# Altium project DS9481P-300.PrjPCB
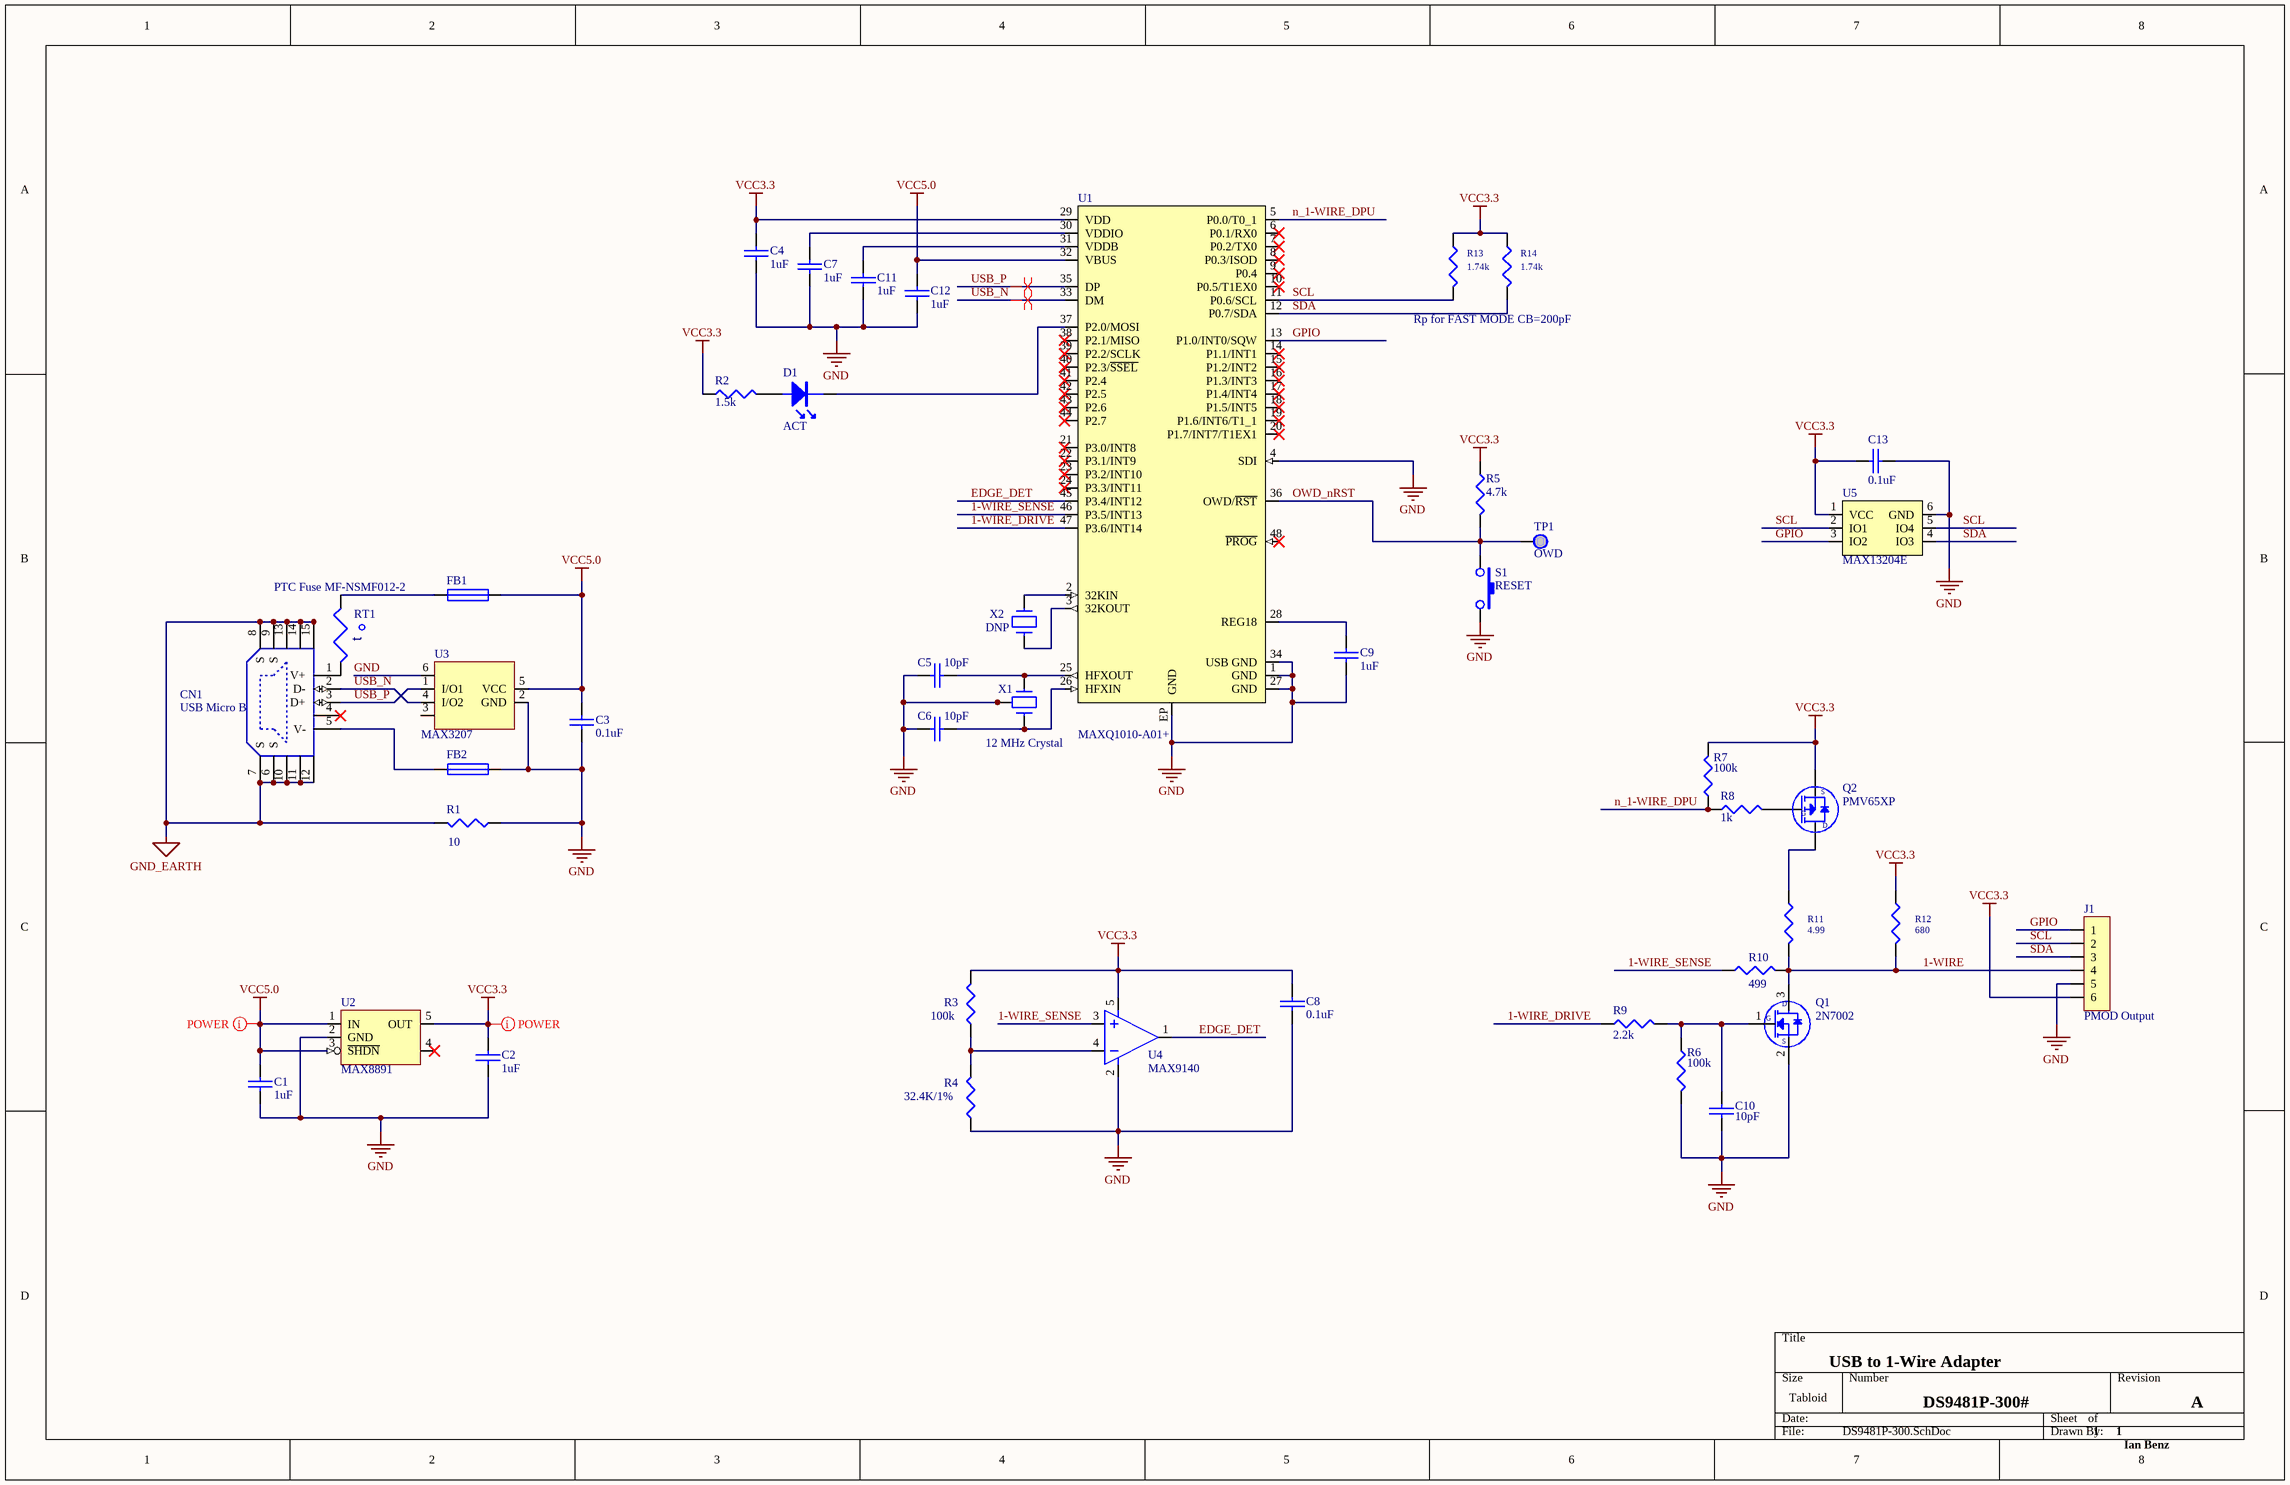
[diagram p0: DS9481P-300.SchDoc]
1 sheet, 44 parts. Net scope: global (net labels, ports and power ports of the same name join across sheets).
Board file: DS9481P-300.PcbDoc

## Sheet DS9481P-300.SchDoc
size Tabloid

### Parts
C1  1uF  [CAP0402-3D]
C2  1uF  [CAP0402-3D]
C3  0.1uF  [CAP0402-3D]
C4  1uF  [CAP0402-3D]
C5  10pF  [CAP0603-3D]
C6  10pF  [CAP0603-3D]
C7  1uF  [CAP0402-3D]
C8  0.1uF  [CAP0402-3D]
C9  1uF  [CAP0402-3D]
C10  10pF  [CAP0402-3D]
C11  1uF  [CAP0402-3D]
C12  1uF  [CAP0402-3D]
C13  0.1uF  [CAP0402-3D]
CN1  USB Micro B  [USBMICROB-3D]
D1  ACT  [0603LED-3DORANGE]
FB1  (no value)  [0603-3D]
FB2  (no value)  [0603-3D]
J1  PMOD Output  [SIP6-SOCKET2-RA-3D]
Q1  2N7002  [16001-3D]
Q2  PMV65XP  [16001-3D]
R1  10  [0603-3D]
R2  1.5k  [0402-3D]
R3  100k  [0402-3D]
R4  32.4K/1%  [0402-3D]
R5  4.7k  [0402-3D]
R6  100k  [0402-3D]
R7  100k  [0402-3D]
R8  1k  [0402-3D]
R9  2.2k  [0402-3D]
R10  499  [0402-3D]
R11  4.99  [0805-3D]
R12  680  [0402-3D]
R13  1.74k  [0402-3D]
R14  1.74k  [0402-3D]
RT1  PTC Fuse MF-NSMF012-2  [1206POLYFUSE-3D]
S1  RESET  [RESET9-3d]
TP1  OWD  [SIP1]  (no BOM)
U1  MAXQ1010-A01+  [TQFN48 6MM]
U2  MAX8891  [SC70-5-3D]
U3  MAX3207  [sot23-6-3D]
U4  MAX9140  [SC70-5-3D]
U5  MAX13204E  [TDFN6 2MM .65]
X1  12 MHz Crystal  [FA-238V]
X2  DNP  [M8]

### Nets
GND: C1.2 C2.2 C3.2 C4.2 C5.2 C6.2 C7.2 C8.2 C9.2 C10.1 C11.2 C12.2 C13.2 FB2.2 J1.5 Q1.2 R1.1 R4.1 R6.1 S1.1 U1.1(GND) U1.4(SDI) U1.27(GND) U1.34(USB_GND) U1.EP(GND) U2.2(GND) U3.2(GND) U3.6 U4.2 U5.6(GND) X1.2(G) X1.4(G)
GND_EARTH: CN1.6(S) CN1.7(S) CN1.8(S) CN1.9(S) CN1.10 CN1.11 CN1.12 CN1.13 CN1.14 CN1.15 CN1.16 R1.2
VCC3.3: C2.1 C4.1 C8.1 C13.1 J1.6 Q2.2 R2.1 R3.2 R5.2 R7.2 R12.2 R13.2 R14.2 U1.29(VDD) U2.5(OUT) U4.5 U5.1(VCC)
VCC5.0: C1.1 C3.1 C12.1 FB1.2 U1.32(VBUS) U2.1(IN) U2.3(~{SHDN}) U3.5(VCC)
1-WIRE: J1.4 Q1.3 R10.2 R11.2 R12.1
1-WIRE_DRIVE: R9.2 U1.47(P3.6/INT14)
1-WIRE_SENSE: R10.1 U1.46(P3.5/INT13) U4.3
EDGE_DET: U1.45(P3.4/INT12) U4.1
GPIO: J1.1 U1.13(P1.0/INT0/SQW) U5.3(IO2)
n_1-WIRE_DPU: R7.1 R8.1 U1.5(P0.0/T0_1)
OWD_nRST: R5.1 S1.2 TP1.1 U1.36(OWD/~{RST})
SCL: J1.2 R13.1 U1.11(P0.6/SCL) U5.2(IO1) U5.5(IO4)
SDA: J1.3 R14.1 U1.12(P0.7/SDA) U5.4(IO3)
USB_N: CN1.2(D-) U1.33(DM) U3.4(I/O2)
USB_P: CN1.3(D+) U1.35(DP) U3.1(I/O1)
NetC5_1: C5.1 U1.25(HFXOUT) X1.1(X1)
NetC6_1: C6.1 U1.26(HFXIN) X1.3(X2)
NetC7_1: C7.1 U1.30(VDDIO)
NetC9_1: C9.1 U1.28(REG18)
NetC10_2: C10.2 Q1.1 R6.2 R9.1
NetC11_1: C11.1 U1.31(VDDB)
NetCN1_1: CN1.1(V+) RT1.1
NetCN1_5: CN1.5(V-) FB2.1
NetD1_1: D1.1 U1.37(P2.0/MOSI)
NetD1_2: D1.2 R2.2
NetFB1_1: FB1.1 RT1.2
NetQ2_1: Q2.1 R8.2
NetQ2_3: Q2.3 R11.1
NetR3_1: R3.1 R4.2 U4.4
NetU1_2: U1.2(32KIN) X2.2
NetU1_3: U1.3(32KOUT) X2.1

Not connected (* = marked no-connect by the designer): CN1 4*; U1 6(P0.1/RX0)* 7(P0.2/TX0)* 8(P0.3/ISOD)* 9(P0.4)* 10(P0.5/T1EX0)* 14(P1.1/INT1)* 15(P1.2/INT2)* 16(P1.3/INT3)* 17(P1.4/INT4)* 18(P1.5/INT5)* 19(P1.6/INT6/T1_1)* 20(P1.7/INT7/T1EX1)* 21(P3.0/INT8)* 22(P3.1/INT9)* 23(P3.2/INT10)* 24(P3.3/INT11)* 38(P2.1/MISO)* 39(P2.2/SCLK)* 40(P2.3/~{SSEL})* 41(P2.4)* 42(P2.5)* 43(P2.6)* 44(P2.7)* 48(~{PROG})*; U2 4*; U3 3

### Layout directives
differential pair: USB_N, USB_P
net class POWER_NETS: VCC3.3, VCC5.0

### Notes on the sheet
- Rp for FAST MODE CB=200pF
- USB to 1-Wire Adapter
- DS9481P-300#
- 1
- A
- Ian Benz

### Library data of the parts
C1 C2 C4 C7 C9 C11 C12 = CAP: CAP CER 1UF 6.3V 20% X5R 0402; Manufacture Name: TDK Corporation; Part Number: C1005X5R0J105M050BB; Internal Part Number: EC1065; Vendor Part Number: 445-1415-1-ND; Vendor: Digi-Key
C3 C8 C13 = CAP: CAP CER 0.1UF 6.3V 10% X5R 0402; Manufacture Name: TDK Corporation; Part Number: C1005X5R0J104K050BA; Internal Part Number: EC1458B; Vendor Part Number: 445-1266-2-ND; Vendor: Digi-Key
C5 C6 = CAP: CAP CER 10PF 50V C0G 0603; Manufacture Name: TDK Corporation; Part Number: C1608C0G1H100D080AA; Internal Part Number: EC0976; Vendor Part Number: 445-1269-1-ND; Vendor: Digi-Key
C10 = CAP: CAP CER 10PF 50V 5% NP0 0402; Manufacture Name: MURATA; Part Number: GRM1555C1H100J; Internal Part Number: ECM0081; Vendor Part Number: 490-5921-1-ND; Vendor: Digi-Key
CN1 = USB-MICRO-B: CONN RCPT STD MICRO USB TYPE B; Internal Part Number: EH1498; Manufacture Name: FCI; Part Number: 10103594-0001LF; Vendor Part Number: 609-4050-1-ND; Vendor: Digi-Key
D1 = LED: LED ORANGE HIGH BRIGHT USS 0603; Manufacture Name: Panasonic; Part Number: LNJ826W83RA; Internal Part Number: ED1021; Vendor Part Number: P13487CT-ND; Vendor: Digi-Key
FB1 FB2 = FUSE1: FERRITE CHIP 220 OHM 2200MA 0603; Part Number: BLM18KG221SN1D; Manufacture Name: Murata Electronics North America; Vendor Part Number: 490-5255-1-ND; Vendor: Digi-Key
J1 = CON6: CONN RCPT .100" 6POS R/A SGL TIN; Manufacture Name: Samtec; Part Number: SSW-106-02-T-S-RA; Vendor Part Number: 82P3428; Vendor: Newark
Q1 = NCHAN FET: MOSFET N-CH 60V 115MA SOT23-3; Manufacture Name: Diodes Inc.; Part Number: 2N7002-7; Internal Part Number: EQ0219
Q2 = PCHAN FET: MOSFET P-CH 20V 2.8A SOT-23; Part Number: PMV65XP,215; Manufacture Name: International Rectifier; Internal Part Number: EQ1054
R1 = RESISTOR: RES SMD 10 OHM 5% 1/10W 0603; Manufacture Name: Vishay Dale; Part Number: CRCW060310R0JNEA; Internal Part Number: ER05060310R0; Vendor Part Number: 541-10GCT-ND; Vendor: Digi-Key
R2 = RESISTOR: RES SMD 1.5K OHM 5% 1/16W 0402; Manufacture Name: Vishay Dale; Part Number: CRCW04021K50JNED; Internal Part Number: ER0504021501; Vendor Part Number: 541-1.5KJCT-ND; Vendor: Digi-Key
R3 = RESISTOR: RES SMD 100K OHM 1% 1/16W 0402; Internal Part Number: ER0104021003; Manufacture Name: Vishay Dale; Part Number: CRCW0402100KFKED; Vendor Part Number: 541-100KLCT-ND; Vendor: Digi-Key
R4 = RESISTOR: RES SMD 32.4K OHM 1% 1/16W 0402; Internal Part Number: ER0104023242; Manufacture Name: Vishay Dale; Part Number: CRCW040232K4FKED; Vendor Part Number: 541-32.4KLCT-ND; Vendor: Digi-Key
R5 = RESISTOR: RES SMD 4.7K OHM 5% 1/10W 0402; Manufacture Name: Panasonic; Part Number: ERJ-2GEJ472X; Internal Part Number: ER0504024701; Vendor Part Number: P4.7KJTR-ND; Vendor: Digi-Key
R6 R7 = RESISTOR: RES SMD 100K OHM 1% 1/16W 0402; Manufacture Name: Vishay Dale; Part Number: CRCW0402100KFKED; Internal Part Number: ER0104021003; Vendor Part Number: 541-100KLCT-ND; Vendor: Digi-Key
R8 = RESISTOR: RES SMD 1K OHM 5% 1/16W 0402; Manufacture Name: Vishay Dale; Part Number: CRCW04021K00JNED; Internal Part Number: ER0504021001; Vendor Part Number: 541-1.0KJCT-ND; Vendor: Digi-Key
R9 = RESISTOR: RES SMD 2.2K OHM 5% 1/10W 0402; Manufacture Name: Panasonic; Part Number: ERJ-2GEJ222X; Internal Part Number: ER0504022201; Vendor Part Number: P2.2KJTR-ND; Vendor: Digi-Key
R10 = RESISTOR: RES SMD 499 OHM 1% 1/16W 0402; Manufacture Name: Vishay Dale; Part Number: CRCW0402499RFKED; Internal Part Number: ER0104024990; Vendor Part Number: 541-499LCT-ND; Vendor: Digi-Key
R11 = RESISTOR: RES SMD 4.99 OHM 1% 1/8W 0805; Manufacture Name: Vishay Dale; Part Number: CRCW08054R99FKEA; Internal Part Number: ER0108054R99; Vendor Part Number: 541-4.99CCCT-ND; Vendor: Digi-Key
R12 = RESISTOR: RES SMD 680 OHM 5% 1/10W 0402; Manufacture Name: Panasonic; Part Number: ERJ-2GEJ681X; Internal Part Number: ER0504026800; Vendor Part Number: P680JCT-ND; Vendor: Digi-Key
R13 R14 = RESISTOR: RES SMD 1.74K OHM 1% 1/10W 0402; Manufacture Name: Panasonic Electronic Components; Part Number: ERJ-2RKF1741X; Internal Part Number: ER0104021741; Vendor Part Number: P1.74KLTR-ND; Vendor: Digi-Key
RT1 = THERMISTOR: PTC Fuse 1206; Manufacture Name: Bourns Inc.; Internal Part Number: EH1032
S1 = SW-PB: SWITCH TACTILE SPST-NO 0.05A 12V; Manufacture Name: Omron Electronics Inc; Part Number: B3U-1000P; Internal Part Number: EH1359; Vendor Part Number: SW1020CT-ND; Vendor: Digi-Key
TP1 = TP: CONN HEADER 1POS .100 VERT GOLD; Manufacture Name: Molex; Internal Part Number: EH0072; Part Number: 0022284363; Vendor Part Number: WM50016-36-ND; Vendor: Digi-Key
U1 = MAXQ1010: Security Token Microcontroller with RTC and USB; Manufacture Name: Maxim Integrated
U2 = MAX8891: High PSRR, Low-Dropout, 150mA  Linear Regulator; Manufacture Name: Maxim Integrated; Part Number: MAX8891EXK33+
U3 = MAX3207E: Dual High-Speed  Differential ESD-Protection IC; Manufacture Name: Maxim Integrated; Part Number: MAX3207EAUT+
U4 = OPAMP: 40ns Single-Supply Comparator; Manufacture Name: Maxim Integrated; Part Number: MAX9140AAXK+
U5 = MAX13204: 4 Channel +/- 30kv ESD Protector; Manufacture Name: Maxim Integrated; Part Number: MAX13204EALT+
X1 = CRYSTAL3: CRYSTAL 12MHZ 10PF SMD; Manufacture Name: EPSON; Part Number: FA-238V 12.0000MB-K3; Vendor Part Number: SER3682TR-ND; Vendor: Digi-Key
X2 = CRYSTAL: Do Not Populate (3.20x1.50mm)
